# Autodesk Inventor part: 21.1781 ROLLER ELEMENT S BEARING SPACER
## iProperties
Created: 2007-05
Part Number: 21.1781 ROLLER ELEMENT S BEARING SPACER
Material: Aluminum-6061
Document SubType Name: Modeling
Designer: Andy Moles
Density: 2.71 g/cm^3
Author: Andy Moles
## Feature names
1. Extrusion1
2. Extrusion2
3. Mirror1
